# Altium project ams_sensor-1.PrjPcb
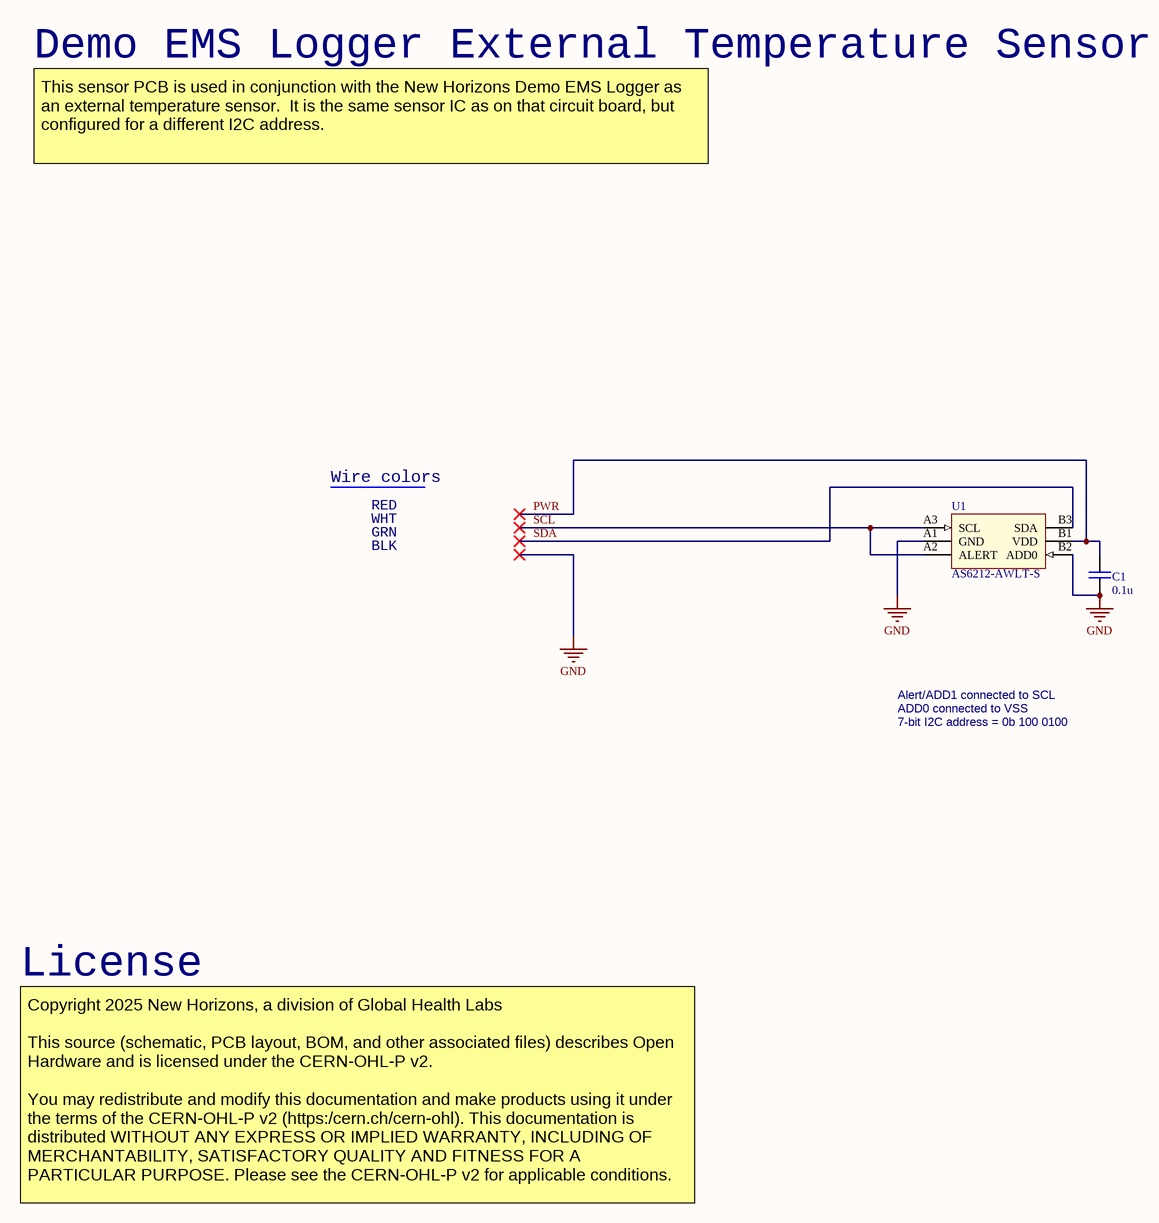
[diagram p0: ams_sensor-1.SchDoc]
nhToday: 2025-06-03; nhProjRev: 2.1; nhProjName: AMS Sensor; nhEngPhone: 808-989-0977; nhEngName: Rod Hinman; nhEngEmail: rhinman@nhgh.org
1 sheet, 2 parts. Net scope: global (net labels, ports and power ports of the same name join across sheets).
Board file: ams_sensor-1.PcbDoc

## Sheet ams_sensor-1.SchDoc: Insert Title
size B; DrawnBy: Insert Name; Organization: NH-GG; DocumentNumber: 1; Revision: 1; SheetNumber: 1; SheetTotal: 1; nhSheetName: sensor

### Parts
C1  value_text: 0.1u  [CAPC1005X55[0402]]  (hidden comment: 10V X7R 0402)
U1  manufacturer_pn: AS6212-AWLT-S  [AMS_BGA6C40P3X2_150X102X60]  (hidden comment: AMS_AS621x)

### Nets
GND: C1.2 U1.A1(GND) U1.B2(ADD0)
PWR: C1.1 U1.B1(VDD)
SCL: U1.A2(ALERT) U1.A3(SCL)
SDA: U1.B3(SDA)

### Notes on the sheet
- Demo EMS Logger External Temperature Sensor
- This sensor PCB is used in conjunction with the New Horizons Demo EMS Logger as an external temperature sensor.  It is the same sensor IC as on that circuit board, but configured for a different I2C address.
- Wire colors
- RED
- WHT
- GRN
- BLK
- Alert/ADD1 connected to SCL
- ADD0 connected to VSS
- 7-bit I2C address = 0b 100 0100
- License
- Copyright 2025 New Horizons, a division of Global Health Labs
  This source (schematic, PCB layout, BOM, and other associated files) describes Open Hardware and is licensed under the CERN-OHL-P v2.
  You may redistribute and modify this documentation and make products using it under the terms of the CERN-OHL-P v2 (https:/cern.ch/cern-ohl). This documentation is distributed WITHOUT ANY EXPRESS OR IMPLIED WARRANTY, INCLUDING OF MERCHANTABILITY, SATISFACTORY QUALITY AND FITNESS FOR A PARTICULAR PURPOSE. Please see the CERN-OHL-P v2 for applicable conditions.

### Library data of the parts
C1 = CAP-00140: 0.1µF ±10% 10V Ceramic Capacitor X7R 0402 (1005 Metric); manufacturer: Samsung Electro-Mechanics America, Inc.; manufacturer_pn: CL05B104KP5NNNC; id: 479140; value: 1E-7; reorder_quantity: 0
U1 = ICANA-00040: TEMP SENSOR WLCSP6 I2C; manufacturer: AMS; id: 474864

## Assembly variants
as built: all parts fitted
